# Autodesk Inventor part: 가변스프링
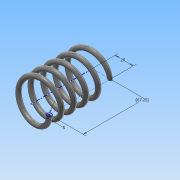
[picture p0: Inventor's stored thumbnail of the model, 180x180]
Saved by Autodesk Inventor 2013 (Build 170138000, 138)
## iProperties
Created: 2018-08
Part Number: 가변스프링
Material: 스테인리스강
Document SubType Name: Modeling
Designer: user
Density: 8.08 g/cm^3
Mass: 98.0401 g
Surface Area: 98.6263 cm^2
Volume: 12.1337 cm^3
Author: user
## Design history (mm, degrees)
sketch "스케치1"
  geometry: L1 (0, 0)-(20, 0); L2 (20, 0)-(20, 67.25); L3 (20, 67.25)-(0, 67.25); L4 (0, 67.25)-(0, 0); C1 r 2.5 at (20, 0)
  constraints: 8 end point, 2 parallel, 1 centre point, 1 coincident, 1 horizontal, 1 perpendicular
  dimensions: "d0" = 20 distance of L2.end L3.end; "d2" = 67.25 distance of L1.end L2.end (derived); "d3" = 5 diameter of C1
feature "코일1" pitch "d4" = 10; turns "d6" = 5; dims "d5" = 67.25 (= d2), "d7" = 0, angle "d8" = 90 deg, angle "d9" = 90 deg, "d10" = 0, "d11" = 0
sketch "스케치2"
  geometry: L1 (-22.5, 0)-(-17.5, 0) reference; L2 (-22.5, 0)-(-17.5, 0) reference; 1 further point
  constraints: 2 horizontal alignment
extrude "돌출1" cut sketch "스케치2" distance "d12" = 10; taper "d13" = 0 deg
node "작업 평면1"
sketch "스케치3"
  geometry: L1 (22.5, 0)-(17.5, 0) reference; 1 further point
  constraints: 1 horizontal alignment
extrude "돌출2" cut sketch "스케치3" distance "d14" = 10; taper "d15" = 0 deg
node "솔리드1"
node "절단 모서리 투영1"
node "절단 모서리 투영2"
node "절단 모서리 투영3"
